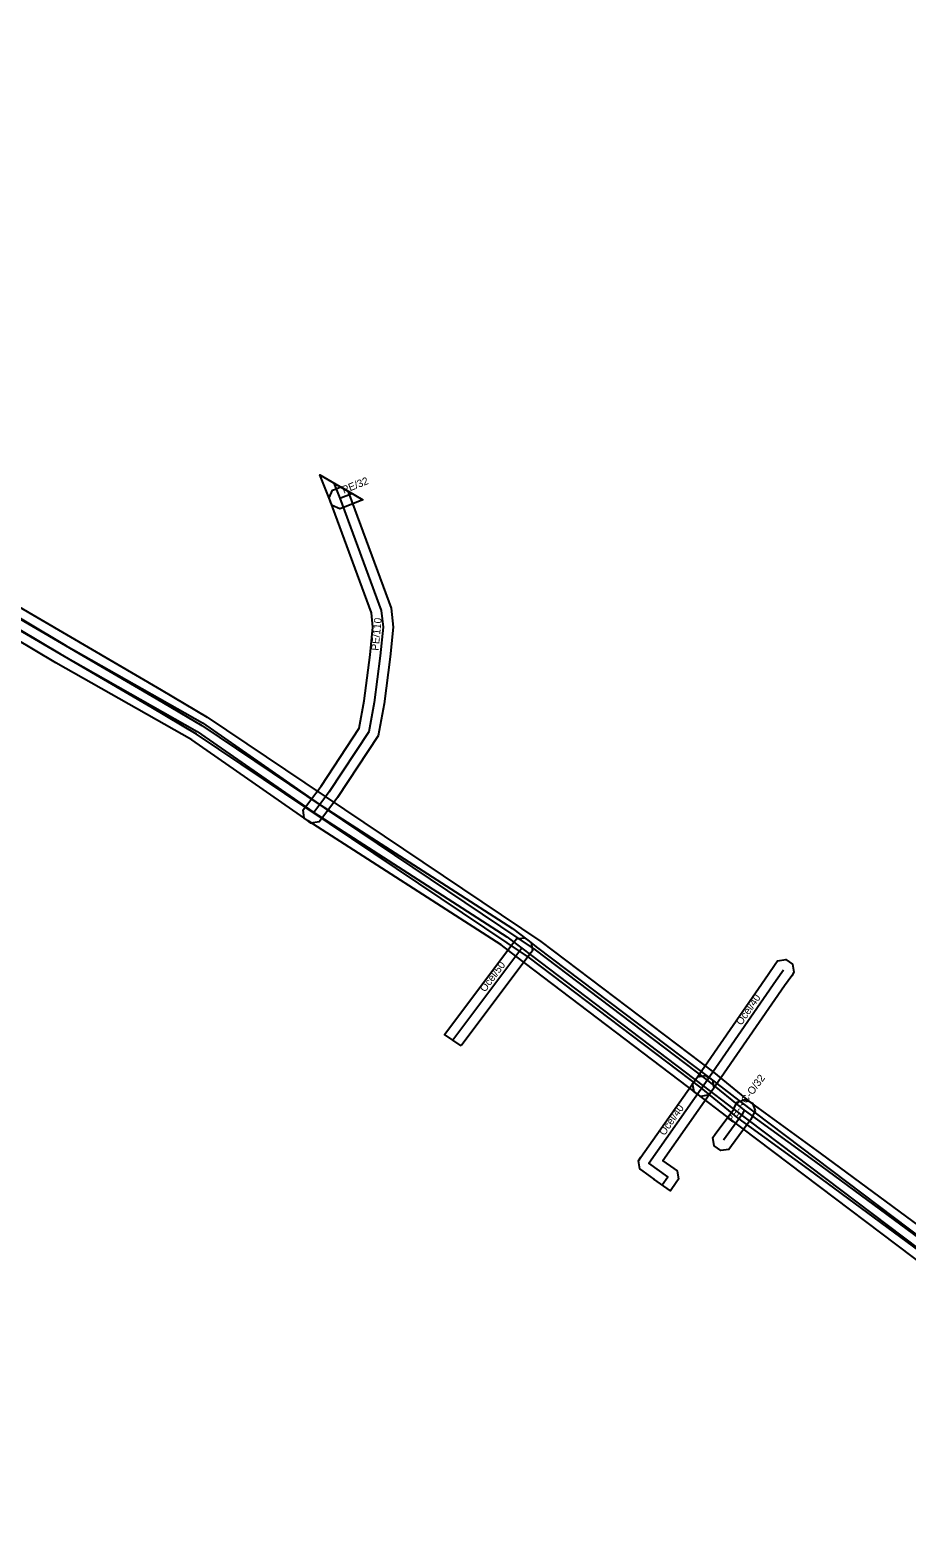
# Model space of a CAD drawing. Extents: x -749340 to -748632, y -965391 to -964902.
# Drawn here: x -748895.1 to -748807.4, y -965252.2 to -965101.5 of the extents above; entities that cross this region are included whole.
import ezdxf

# ---------------------------------------------------------------- set-up
doc = ezdxf.new("R2010")
doc.units = 0
for name, color, linetype in [('1', 7, 'Continuous'), ('14', 7, 'Continuous'), ('18', 7, 'Continuous'), ('20', 7, 'Continuous'), ('24', 7, 'Continuous'), ('28', 7, 'Continuous'), ('30', 7, 'Continuous')]:
    doc.layers.add(name, color=color, linetype=linetype)

msp = doc.modelspace()

# ---------------------------------------------------------------- linework, layer by layer
at = {"layer": '1'}
for points in [[(-748997.7, -965101.46), (-748982.49, -965110.26), (-748969.03, -965118), (-748960.43, -965122.95), (-748950.92, -965128.42), (-748944.23, -965132.27), (-748916.63, -965148.15), (-748909.18, -965152.43), (-748903.91, -965155.58), (-748891.49, -965162.98), (-748877.84, -965170.71), (-748866.16, -965178.84), (-748846.84, -965191.26), (-748845.3, -965192.43), (-748844.32, -965193.17), (-748827.15, -965206.19), (-748824.19, -965208.44), (-748797.89, -965228.31)], [(-748799.1, -965229.9), (-748825.4, -965210.03), (-748828.36, -965207.78), (-748845.53, -965194.76), (-748846.5, -965194.02), (-748847.98, -965192.9), (-748867.27, -965180.5), (-748878.9, -965172.41), (-748892.49, -965164.71), (-748904.93, -965157.3), (-748910.19, -965154.16), (-748917.63, -965149.88), (-748945.23, -965134), (-748951.91, -965130.16), (-748961.43, -965124.68), (-748970.03, -965119.74), (-748983.49, -965111.99)], [(-748903.48, -965154.85), (-748881.97, -965167.4), (-748877.36, -965170.14), (-748843.99, -965192.56), (-748826.74, -965205.62), (-748823.05, -965208.63), (-748816.06, -965213.71), (-748766.07, -965250.55)], [(-748767.26, -965252.16), (-748817.24, -965215.32), (-748824.27, -965210.21), (-748827.98, -965207.19), (-748845.15, -965194.19), (-748878.43, -965171.83), (-748882.98, -965169.12), (-748904.49, -965156.58)]]:
    msp.add_lwpolyline(points, dxfattribs=at)
for points in [[(-748865.02, -965148.59), (-748866.11, -965145.92), (-748863.29, -965147.54), (-748863.16, -965147.87), (-748858.98, -965159.24), (-748858.78, -965161.15), (-748859.07, -965164.11), (-748859.67, -965168.81), (-748860.25, -965171.99), (-748864.33, -965178.17), (-748864.9, -965178.94), (-748865.92, -965180.28), (-748866.17, -965180.6), (-748866.99, -965180.72), (-748867.32, -965180.46), (-748867.65, -965180.21), (-748867.76, -965179.39), (-748867.51, -965179.06), (-748866.5, -965177.74), (-748865.97, -965177.03), (-748862.15, -965171.23), (-748861.65, -965168.51), (-748861.05, -965163.89), (-748860.79, -965161.15), (-748860.94, -965159.7)], [(-748864.01, -965147.12), (-748861.8, -965148.4), (-748863.72, -965149.16), (-748864.11, -965149.31), (-748864.87, -965148.98), (-748865.02, -965148.6), (-748865.17, -965148.21), (-748864.84, -965147.45), (-748864.46, -965147.3)], [(-748851.98, -965202.99), (-748853.63, -965201.85), (-748846.7, -965192.62), (-748846.45, -965192.29), (-748845.63, -965192.18), (-748845.3, -965192.43), (-748844.97, -965192.67), (-748844.85, -965193.49), (-748845.1, -965193.83)], [(-748828.82, -965206.76), (-748828.58, -965206.42), (-748821.28, -965195.86), (-748820.57, -965194.83), (-748820.33, -965194.49), (-748819.52, -965194.34), (-748819.18, -965194.58), (-748818.84, -965194.82), (-748818.69, -965195.63), (-748818.92, -965195.97), (-748819.63, -965197), (-748826.94, -965207.55), (-748827.17, -965207.89), (-748827.99, -965208.04), (-748828.33, -965207.81), (-748828.67, -965207.57)], [(-748830.47, -965216.64), (-748831.05, -965217.46), (-748832.69, -965216.32), (-748832.68, -965216.3), (-748833.78, -965215.51), (-748834.11, -965215.27), (-748834.25, -965214.46), (-748834.01, -965214.12), (-748828.58, -965206.41), (-748828.34, -965206.07), (-748827.52, -965205.93), (-748827.18, -965206.17), (-748826.84, -965206.41), (-748826.7, -965207.22), (-748826.94, -965207.56), (-748831.8, -965214.46), (-748830.7, -965215.25), (-748830.37, -965215.49), (-748830.23, -965216.3)], [(-748822.58, -965209.49), (-748822.76, -965209.86), (-748823, -965210.35), (-748824.94, -965212.99), (-748825.19, -965213.33), (-748826.01, -965213.45), (-748826.34, -965213.21), (-748826.68, -965212.96), (-748826.8, -965212.14), (-748826.56, -965211.81), (-748824.72, -965209.31), (-748824.56, -965208.98), (-748824.38, -965208.61), (-748823.59, -965208.34), (-748823.22, -965208.52), (-748822.85, -965208.7)]]:
    msp.add_lwpolyline(points, close=True, dxfattribs=at)
at = {"layer": '14'}
for points in [[(-748864.7, -965146.73), (-748864.09, -965148.23), (-748859.96, -965159.47), (-748859.78, -965161.15), (-748860.06, -965164), (-748860.66, -965168.66), (-748861.2, -965171.61), (-748865.15, -965177.6), (-748865.7, -965178.34), (-748866.71, -965179.67)], [(-748864.09, -965148.23), (-748862.91, -965147.76)]]:
    msp.add_lwpolyline(points, dxfattribs=at)
at = {"layer": '18'}
for points in [[(-748982.99, -965111.13), (-748969.53, -965118.87), (-748960.93, -965123.81), (-748951.42, -965129.29), (-748944.73, -965133.13), (-748917.13, -965149.01), (-748909.68, -965153.3), (-748904.42, -965156.44), (-748891.99, -965163.85), (-748878.37, -965171.56), (-748866.71, -965179.67), (-748847.41, -965192.08), (-748845.9, -965193.22), (-748844.92, -965193.96), (-748827.76, -965206.98), (-748824.79, -965209.23), (-748798.49, -965229.11)], [(-748845.9, -965193.22), (-748852.8, -965202.42)], [(-748827.76, -965206.98), (-748820.46, -965196.43), (-748819.75, -965195.4)], [(-748831.87, -965216.89), (-748831.29, -965216.06), (-748833.19, -965214.7), (-748827.76, -965206.98)]]:
    msp.add_lwpolyline(points, dxfattribs=at)
at = {"layer": '24'}
msp.add_lwpolyline([(-748823.66, -965209.42), (-748823.86, -965209.83), (-748825.75, -965212.4)], dxfattribs=at)
at = {"layer": '28'}
msp.add_lwpolyline([(-748969.37, -965118.02), (-748960.45, -965123.17), (-748951.28, -965128.45), (-748944.25, -965132.48), (-748920.54, -965146.06), (-748916.62, -965148.35), (-748903.99, -965155.72), (-748882.47, -965168.26), (-748877.9, -965170.98), (-748844.57, -965193.37), (-748827.36, -965206.4), (-748823.66, -965209.42), (-748816.65, -965214.51), (-748766.66, -965251.35)], dxfattribs=at)

# ---------------------------------------------------------------- texts
at = {"layer": '20'}
for s, rotation, p in [('PE/32', 21.6271, (-748863.7, -965147.8)), ('PE/110', 84.3889, (-748860.23, -965163.51)), ('Ocel/50', 53.0938, (-748849.58, -965197.66)), ('Ocel/40', 55.3294, (-748823.95, -965200.99)), ('Ocel/40', 54.8344, (-748831.64, -965212.01))]:
    msp.add_text(s, height=0.75, rotation=rotation, dxfattribs=at).set_placement(p)
at = {"layer": '30'}
msp.add_text('PE-RC-O/32', height=0.75, rotation=53.6689, dxfattribs=at).set_placement((-748824.87, -965210.73))

doc.saveas('drawing.dxf')
